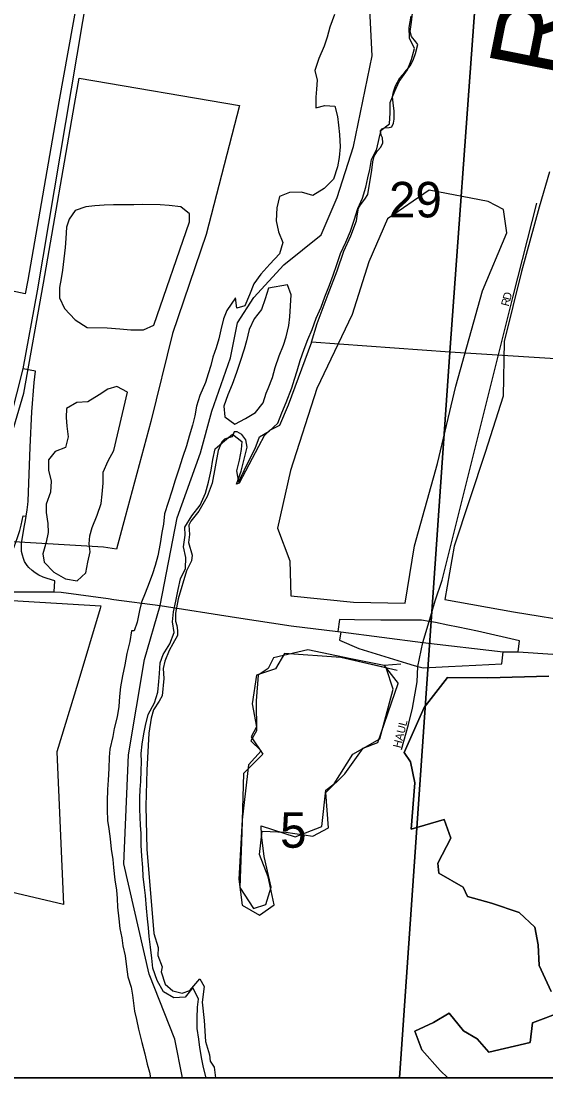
# Model space of a CAD drawing. Extents: x 0 to 34, y -6.2 to 22.
# Drawn here: x 6.003 to 6.622, y 14.39 to 15.636 of the extents above; entities that cross this region are included whole.
import ezdxf

# ---------------------------------------------------------------- set-up
doc = ezdxf.new("R2010")
doc.units = 0
for name, color, linetype in [('GM_X_City_Street', 7, 'Continuous'), ('GM_X_City_Street_Text', 7, 'Continuous'), ('GM_X_Corporation', 7, 'Continuous'), ('GM_X_Interchange_Ramps', 7, 'Continuous'), ('GM_X_Interstate_Route', 7, 'Continuous'), ('GM_X_Major_River', 7, 'Continuous'), ('GM_X_Major_River_Text', 7, 'Continuous'), ('GM_X_Minor_Lake', 7, 'Continuous'), ('GM_X_Section', 7, 'Continuous'), ('GM_X_Section_Text', 7, 'Continuous'), ('GM_X_State_Route', 7, 'Continuous'), ('GM_X_Township', 7, 'Continuous'), ('SH_Data', 7, 'Continuous')]:
    doc.layers.add(name, color=color, linetype=linetype)

msp = doc.modelspace()

# ---------------------------------------------------------------- linework, layer by layer
at = {"layer": 'GM_X_City_Street'}
msp.add_lwpolyline([(6.4516, 14.7775), (6.4595, 14.8069), (6.4644, 14.8262), (6.4697, 14.8571), (6.4706, 14.8751), (6.4766, 14.9035), (6.484, 14.9282), (6.4913, 14.9528), (6.4994, 14.9771), (6.583, 15.312), (6.6109, 15.4214)], dxfattribs=at)
at = {"layer": 'GM_X_Corporation'}
for points in [[(5.4833, 14.3902), (9.0755, 14.3902), (9.0755, 21.1902), (4.181, 21.1902)], [(6.0863, 15.7569), (6.0473, 15.541), (6.0106, 15.3305), (6.0078, 15.3144), (5.8578, 15.3464), (5.8706, 15.5168), (5.8395, 15.5185), (5.8415, 15.5423)], [(5.9675, 15.0677), (6.0061, 15.1973), (6.0293, 15.3272), (6.066, 15.5377), (6.0715, 15.5687), (6.2604, 15.5367), (6.2211, 15.3845), (6.1813, 15.2679), (6.1557, 15.1641), (6.1255, 15.0516), (6.1152, 15.0137), (6.0999, 15.016), (5.9475, 15.0249), (5.9675, 15.0677)], [(5.7838, 14.6859), (5.8622, 14.7617), (5.8945, 14.7931), (5.9217, 14.8222), (5.9352, 14.8512), (5.9529, 14.9009), (5.9722, 14.954), (6.0969, 14.9467), (6.0961, 14.9436), (6.0699, 14.8554), (6.045, 14.7747), (6.0527, 14.5945), (5.7641, 14.6624), (5.7838, 14.6859)]]:
    msp.add_lwpolyline(points, dxfattribs=at)
at = {"layer": 'GM_X_Interchange_Ramps'}
for points in [[(6.0417, 14.9633), (6.0425, 14.9763), (6.0337, 14.9788), (6.0288, 14.9805), (6.0238, 14.9829), (6.0194, 14.9856), (6.0157, 14.9884), (6.012, 14.9919), (6.0098, 14.9943), (6.0069, 14.9991), (6.0055, 15.0025), (6.0043, 15.0064), (6.0035, 15.0107), (6.0032, 15.0145), (6.0035, 15.0202), (6.0043, 15.0277), (6.0067, 15.0416), (6.008, 15.0474), (6.0089, 15.0523), (6.0101, 15.06), (6.0108, 15.0662), (6.0112, 15.07), (6.0134, 15.1338), (6.0155, 15.1755), (6.0182, 15.2102), (6.0199, 15.2235), (6.0052, 15.2262)], [(5.9741, 14.9631), (5.9777, 14.9734), (5.9919, 15.0102), (5.9945, 15.0161), (5.9967, 15.0218), (5.9985, 15.0271), (5.9998, 15.031), (6.0012, 15.0357), (6.0028, 15.0418), (6.004, 15.0475), (6.0051, 15.053), (6.0089, 15.0523)], [(6.484, 14.9282), (6.4751, 14.9297), (6.427, 14.9299), (6.3959, 14.9302), (6.3784, 14.9306), (6.3764, 14.9166)], [(6.5891, 14.8924), (6.5907, 14.9054), (6.5411, 14.9167), (6.5182, 14.9214), (6.5059, 14.9239), (6.4916, 14.9269), (6.484, 14.9282)], [(6.3797, 14.9159), (6.3784, 14.9061), (6.4011, 14.8965), (6.4574, 14.8793), (6.4664, 14.8762), (6.4706, 14.8751)], [(6.4706, 14.8751), (6.4769, 14.8735), (6.5067, 14.8752), (6.539, 14.8766), (6.5699, 14.8783), (6.5712, 14.8923)]]:
    msp.add_lwpolyline(points, dxfattribs=at)
at = {"layer": 'GM_X_Interstate_Route'}
msp.add_lwpolyline([(5.9164, 14.9622), (5.9164, 14.9622), (5.9488, 15.0343), (5.9755, 15.1099), (6.0052, 15.2262), (6.0222, 15.3181), (6.0956, 15.7552), (6.1327, 15.9696), (6.1711, 16.1965)], dxfattribs=at)
at = {"layer": 'GM_X_Major_River'}
for points in [[(6.3723, 15.6439), (6.3669, 15.6291), (6.3638, 15.617), (6.3604, 15.6064), (6.3538, 15.592), (6.3492, 15.578), (6.3518, 15.5666), (6.3513, 15.556), (6.3505, 15.5465), (6.3504, 15.534), (6.3611, 15.5365), (6.3728, 15.5357), (6.3761, 15.5236), (6.3772, 15.5133), (6.3783, 15.5023), (6.379, 15.4879), (6.3781, 15.4753), (6.3758, 15.4643), (6.3712, 15.4499), (6.3601, 15.4386), (6.3468, 15.4304), (6.3336, 15.4346), (6.3195, 15.4339), (6.3074, 15.4294), (6.3043, 15.4158), (6.3038, 15.4006), (6.3064, 15.3877), (6.3116, 15.3751), (6.3074, 15.3619), (6.2963, 15.3494), (6.2856, 15.3377), (6.2772, 15.3264), (6.2722, 15.3135), (6.2668, 15.3006), (6.2573, 15.2977), (6.2555, 15.3098), (6.2456, 15.2951), (6.2417, 15.2852), (6.2383, 15.2723), (6.2359, 15.2617)], [(6.2624, 15.131), (6.2601, 15.1185), (6.257, 15.106), (6.2592, 15.0927), (6.2657, 15.1063), (6.2722, 15.1192), (6.2787, 15.1324), (6.2841, 15.1461), (6.2955, 15.1528), (6.3054, 15.1619), (6.3104, 15.1744), (6.3154, 15.1865), (6.3219, 15.2039), (6.3254, 15.2138), (6.3285, 15.2236), (6.332, 15.2361), (6.3366, 15.2494), (6.3408, 15.2607), (6.3462, 15.2725), (6.3509, 15.2857), (6.3566, 15.299), (6.3612, 15.3111), (6.3666, 15.3247), (6.3709, 15.3365), (6.3751, 15.349), (6.3793, 15.3622), (6.3859, 15.3755), (6.3912, 15.3883), (6.3955, 15.4016), (6.4001, 15.4152), (6.4055, 15.4273), (6.4094, 15.4402), (6.4117, 15.4512), (6.414, 15.4611), (6.416, 15.4728), (6.4225, 15.4857), (6.4249, 15.4978), (6.4276, 15.5077), (6.4371, 15.5152), (6.4379, 15.5281), (6.438, 15.5403), (6.4434, 15.5535), (6.4488, 15.5649), (6.4583, 15.5785), (6.4633, 15.591), (6.4668, 15.6039), (6.4608, 15.616), (6.4605, 15.6286), (6.4629, 15.6418)], [(6.292, 15.1976), (6.2943, 15.2029), (6.2993, 15.2158), (6.3024, 15.2279), (6.307, 15.2416), (6.3124, 15.2541), (6.3155, 15.2639), (6.3186, 15.2772), (6.3198, 15.2874), (6.3215, 15.3132), (6.317, 15.325), (6.2946, 15.3214)], [(6.2946, 15.3214), (6.2908, 15.3088), (6.2865, 15.2963), (6.2777, 15.285), (6.2716, 15.2725), (6.2685, 15.2593), (6.2658, 15.2494), (6.2611, 15.2346), (6.2569, 15.2218), (6.2519, 15.2077), (6.2465, 15.1953), (6.2419, 15.182), (6.2429, 15.1695), (6.255, 15.161), (6.2676, 15.1674), (6.2793, 15.1746), (6.2881, 15.1859), (6.292, 15.1976)], [(6.2359, 15.2617), (6.2328, 15.2511), (6.229, 15.2398), (6.2266, 15.2299), (6.2235, 15.2201), (6.2201, 15.2102), (6.2135, 15.1947), (6.2097, 15.1822), (6.2077, 15.1708), (6.205, 15.1598), (6.2011, 15.1466), (6.1977, 15.1352), (6.193, 15.1216), (6.1888, 15.1079), (6.1845, 15.0947), (6.1807, 15.0818), (6.1764, 15.0685), (6.1718, 15.0553), (6.1706, 15.0431), (6.1686, 15.0333), (6.167, 15.0204), (6.1639, 15.0056), (6.1608, 14.9942), (6.1577, 14.9844), (6.1539, 14.9738), (6.1493, 14.9617), (6.145, 14.9511), (6.1423, 14.9412), (6.1396, 14.9276), (6.1361, 14.9173)], [(6.2209, 14.3902), (6.2179, 14.4026), (6.2161, 14.4121), (6.2135, 14.4258), (6.2124, 14.4357), (6.2106, 14.4482), (6.2103, 14.4604), (6.2108, 14.4736), (6.2119, 14.4831), (6.2052, 14.4968), (6.1964, 14.4855), (6.1828, 14.4844), (6.1707, 14.4917), (6.1632, 14.505), (6.158, 14.5195), (6.1569, 14.5313), (6.1555, 14.5442), (6.154, 14.5567), (6.153, 14.567), (6.1519, 14.5776), (6.1508, 14.5901), (6.1494, 14.6053), (6.1483, 14.6148), (6.1469, 14.6277), (6.1462, 14.6383), (6.1451, 14.6516), (6.1445, 14.6645), (6.1445, 14.6782), (6.1438, 14.6881), (6.1431, 14.6976), (6.1428, 14.7071), (6.1429, 14.7203), (6.1433, 14.7302), (6.1441, 14.7397), (6.1446, 14.7526), (6.1447, 14.7628), (6.1443, 14.7727), (6.1455, 14.7837), (6.1475, 14.7958), (6.1495, 14.8057), (6.1526, 14.8186), (6.1602, 14.8322), (6.1641, 14.8451), (6.1653, 14.8576), (6.1661, 14.8671), (6.167, 14.8796), (6.1704, 14.8894), (6.1781, 14.9019), (6.1835, 14.9152), (6.1813, 14.9277), (6.1825, 14.9398), (6.1852, 14.9523), (6.1879, 14.966), (6.191, 14.9785), (6.1968, 14.9906), (6.1972, 15.0039), (6.1943, 15.0164), (6.1963, 15.0301), (6.1959, 15.0396), (6.204, 15.0528), (6.2139, 15.0656), (6.2204, 15.0796), (6.2239, 15.0925), (6.227, 15.1066), (6.229, 15.1194), (6.2317, 15.132), (6.2428, 15.1414), (6.2523, 15.1493), (6.2632, 15.1405), (6.2624, 15.131)], [(6.1361, 14.9173), (6.1331, 14.9174), (6.1311, 14.9045), (6.1276, 14.8904), (6.1253, 14.8772), (6.1225, 14.8643), (6.1202, 14.8514), (6.119, 14.84), (6.1182, 14.8279), (6.1162, 14.8157), (6.1127, 14.8021), (6.1111, 14.7926), (6.1076, 14.7779), (6.1068, 14.7684), (6.1064, 14.7551), (6.1055, 14.7411), (6.1047, 14.7301), (6.1042, 14.7164), (6.1042, 14.7061), (6.1049, 14.6936), (6.1063, 14.6837), (6.1078, 14.672), (6.1092, 14.6598), (6.111, 14.6477), (6.1117, 14.6382), (6.1135, 14.6237), (6.1154, 14.6116), (6.116, 14.6017), (6.1167, 14.5915), (6.1182, 14.5778), (6.1193, 14.5664), (6.1215, 14.5554), (6.1229, 14.5459), (6.1255, 14.5341), (6.1273, 14.5212), (6.1288, 14.5094), (6.1325, 14.4973), (6.1343, 14.4878), (6.1365, 14.4688), (6.1391, 14.4589), (6.1413, 14.4475), (6.1453, 14.4319), (6.1487, 14.4186), (6.1516, 14.4065), (6.1542, 14.3969), (6.1554, 14.3902)]]:
    msp.add_lwpolyline(points, dxfattribs=at)
at = {"layer": 'GM_X_Minor_Lake'}
for points in [[(6.6259, 15.4584), (6.6139, 15.4167), (6.593, 15.3408), (6.5725, 15.2585), (6.5713, 15.1939), (6.5501, 15.1276), (6.5135, 15.0172), (6.5025, 14.9542), (6.5836, 14.9395), (6.6609, 14.927), (6.7156, 14.9356), (6.7213, 15.0046), (6.7237, 15.1064), (6.705, 15.2139), (6.7037, 15.3233), (6.6995, 15.392), (6.6809, 15.4476)], [(6.5537, 15.4234), (6.4839, 15.4369), (6.4348, 15.403), (6.4129, 15.3522), (6.3932, 15.2903), (6.3517, 15.2028), (6.3205, 15.1061), (6.3053, 15.0382), (6.3199, 14.9998), (6.3208, 14.9584), (6.3947, 14.9509), (6.4558, 14.9499), (6.4668, 15.0174), (6.4939, 15.1145), (6.5156, 15.2056), (6.547, 15.3182), (6.5758, 15.3865), (6.5718, 15.4142)], [(6.2016, 15.3993), (6.2014, 15.4088), (6.1913, 15.4173), (6.1773, 15.4187), (6.1667, 15.4196), (6.1458, 15.4198), (6.1356, 15.4196), (6.1216, 15.4194), (6.1117, 15.4196), (6.1007, 15.4193), (6.0897, 15.4183), (6.0791, 15.4173), (6.0665, 15.413), (6.0596, 15.4028), (6.0564, 15.393), (6.0555, 15.3797), (6.0549, 15.3691), (6.0515, 15.3425), (6.0499, 15.3327), (6.0482, 15.3221), (6.0481, 15.3099), (6.054, 15.2973), (6.0667, 15.2838), (6.0809, 15.2749), (6.1044, 15.2746), (6.1192, 15.2733), (6.1324, 15.2723), (6.1472, 15.2721), (6.1594, 15.2777)], [(6.5718, 15.4142), (6.5537, 15.4234)], [(6.1594, 15.2777), (6.2016, 15.3993)], [(6.1284, 15.1987), (6.1156, 15.2053), (6.1053, 15.2021), (6.095, 15.1954), (6.0816, 15.1872), (6.0684, 15.1866), (6.0565, 15.1792), (6.056, 15.1689), (6.0566, 15.1587), (6.0583, 15.1458), (6.0551, 15.1333), (6.0429, 15.1285), (6.0352, 15.1187), (6.0351, 15.1066), (6.0383, 15.0936), (6.0374, 15.0807), (6.0322, 15.0664), (6.0325, 15.0569), (6.0342, 15.0439), (6.0348, 15.0333), (6.0324, 15.0216), (6.0284, 15.008), (6.0302, 14.9984), (6.0414, 14.9865), (6.0553, 14.9784), (6.0689, 14.9763), (6.0793, 14.9856), (6.0817, 14.9981), (6.0842, 15.0102), (6.0831, 15.0197), (6.084, 15.0292), (6.0868, 15.0391), (6.0927, 15.0538), (6.0971, 15.0674), (6.0983, 15.0784), (6.0997, 15.0913), (6.0998, 15.1042), (6.1057, 15.1178), (6.1123, 15.1298)], [(6.1123, 15.1298), (6.1284, 15.1987)], [(6.4508, 14.8778), (6.4311, 14.8763), (6.3917, 14.8844), (6.3409, 14.8949), (6.3006, 14.8856), (6.2941, 14.8727), (6.2823, 14.8651), (6.2799, 14.8348), (6.2804, 14.7995), (6.2739, 14.7877), (6.286, 14.7759), (6.2711, 14.7592), (6.2635, 14.6943), (6.2597, 14.6245), (6.2637, 14.5937), (6.2838, 14.5819), (6.3013, 14.5943), (6.2943, 14.6274), (6.2838, 14.6536), (6.287, 14.681), (6.3151, 14.6797), (6.3469, 14.675), (6.3655, 14.6848), (6.362, 14.7266), (6.3845, 14.7485), (6.4063, 14.7788), (6.4234, 14.7856), (6.4473, 14.855)], [(6.4332, 14.8736), (6.3799, 14.886), (6.3136, 14.8904), (6.3029, 14.8726), (6.2804, 14.8648), (6.2753, 14.831), (6.2805, 14.804), (6.2743, 14.7923), (6.2879, 14.7717), (6.265, 14.749), (6.2631, 14.6795), (6.2608, 14.6146), (6.277, 14.5899), (6.2914, 14.5944), (6.2976, 14.6149), (6.2895, 14.651), (6.2862, 14.6768), (6.2859, 14.6874), (6.326, 14.6744), (6.3576, 14.6864), (6.362, 14.7293), (6.3719, 14.7368), (6.3941, 14.7717), (6.4257, 14.7898), (6.4416, 14.8486)], [(6.4462, 14.8706), (6.3799, 14.886), (6.3136, 14.8904), (6.3029, 14.8726), (6.2804, 14.8648), (6.2753, 14.831), (6.2805, 14.804), (6.2743, 14.7923), (6.2879, 14.7717), (6.265, 14.749), (6.2631, 14.6795), (6.2608, 14.6146), (6.277, 14.5899), (6.2914, 14.5944), (6.2976, 14.6149), (6.2895, 14.651), (6.2862, 14.6768), (6.2859, 14.6874), (6.326, 14.6744), (6.3576, 14.6864), (6.362, 14.7293), (6.3719, 14.7368), (6.3941, 14.7717), (6.4257, 14.7898), (6.4416, 14.8486)], [(6.4311, 14.8763), (6.4473, 14.855)], [(6.4416, 14.8486), (6.4332, 14.8736)], [(6.6253, 14.8638), (6.5532, 14.8618), (6.5058, 14.8623), (6.4782, 14.8268), (6.4544, 14.7737), (6.462, 14.7627), (6.4671, 14.738), (6.4627, 14.6833), (6.5018, 14.6949), (6.5096, 14.6729), (6.4943, 14.6433), (6.4954, 14.6315), (6.5241, 14.6151), (6.5294, 14.6041), (6.5574, 14.596), (6.59, 14.5852), (6.6088, 14.5677), (6.6125, 14.5472), (6.6139, 14.5225), (6.6281, 14.492)], [(6.6281, 14.492), (6.6139, 14.5225), (6.6125, 14.5472), (6.6088, 14.5677), (6.59, 14.5852), (6.5574, 14.596), (6.5294, 14.6041), (6.5241, 14.6151), (6.4954, 14.6315), (6.4943, 14.6433), (6.5096, 14.6729), (6.5018, 14.6949), (6.4627, 14.6833), (6.4671, 14.738), (6.462, 14.7627), (6.4544, 14.7737), (6.4782, 14.8268), (6.5058, 14.8623), (6.5532, 14.8618), (6.6253, 14.8638)], [(6.6424, 14.4688), (6.6059, 14.4549), (6.6031, 14.4318), (6.5545, 14.4206), (6.5406, 14.4362), (6.5247, 14.4458), (6.5077, 14.4663), (6.4891, 14.4554), (6.467, 14.4452), (6.4753, 14.4232), (6.4971, 14.3988), (6.5062, 14.3902)], [(6.5062, 14.3902), (6.4971, 14.3988), (6.4753, 14.4232), (6.467, 14.4452), (6.4891, 14.4554), (6.5077, 14.4663), (6.5247, 14.4458), (6.5406, 14.4362), (6.5545, 14.4206), (6.6031, 14.4318), (6.6059, 14.4549), (6.6424, 14.4688)]]:
    msp.add_lwpolyline(points, dxfattribs=at)
at = {"layer": 'GM_X_Section'}
for p, q in [((6.2319, 14.3902), (6.449, 14.3902)), ((6.449, 14.3902), (7.4483, 14.3902))]:
    msp.add_line(p, q, dxfattribs=at)
msp.add_lwpolyline([(7.5576, 16.2055), (7.497, 15.1834), (6.5086, 15.2458), (6.5658, 16.0353), (6.5704, 16.0443), (6.5735, 16.0466), (6.5731, 16.0496), (6.5693, 16.0527), (6.5637, 16.0565), (6.5603, 16.0599), (6.5603, 16.0637), (6.5622, 16.0671), (6.5676, 16.0735), (6.582, 16.0863), (6.5935, 16.0976), (6.6121, 16.1149), (6.632, 16.1352), (6.6415, 16.1465), (6.6507, 16.159), (6.658, 16.1722), (6.671, 16.2039), (6.6853, 16.2364), (6.6948, 16.25), (6.6949, 16.2608)], close=True, dxfattribs=at)
for points in [[(6.5658, 16.0353), (6.5086, 15.2458), (6.3451, 15.2574), (6.352, 15.2797), (6.3651, 15.3141), (6.3755, 15.3417), (6.3836, 15.3648), (6.3917, 15.3829), (6.3982, 15.4007), (6.3994, 15.409), (6.4006, 15.4154), (6.4029, 15.4196), (6.4082, 15.426), (6.4117, 15.4316), (6.4164, 15.4604), (6.4176, 15.4702), (6.4192, 15.477), (6.423, 15.4831), (6.4272, 15.4876), (6.4295, 15.4925), (6.4291, 15.4986), (6.4276, 15.5016), (6.4265, 15.5069), (6.4288, 15.5092), (6.4315, 15.5103), (6.4368, 15.5106), (6.4402, 15.5114), (6.4421, 15.5159), (6.4429, 15.5205), (6.4426, 15.5299), (6.4415, 15.5398), (6.4408, 15.547), (6.442, 15.5527), (6.4443, 15.5598), (6.4493, 15.5693), (6.4554, 15.5761), (6.4619, 15.5836), (6.4657, 15.5912), (6.468, 15.598), (6.4707, 15.6086), (6.4685, 15.6116), (6.4632, 15.6181), (6.4617, 15.6238), (6.4633, 15.6347), (6.4657, 15.6559)], [(6.449, 14.3902), (6.5086, 15.2458), (6.3451, 15.2574), (6.3177, 15.1833), (6.3077, 15.1592), (6.2959, 15.1535), (6.2895, 15.1471), (6.2826, 15.1347), (6.2599, 15.0913), (6.2569, 15.0901), (6.2623, 15.1056), (6.2693, 15.1336), (6.2678, 15.1424), (6.2633, 15.1488), (6.2577, 15.1519), (6.2539, 15.1519), (6.2516, 15.1459), (6.2463, 15.1444), (6.2428, 15.1433), (6.2394, 15.1399), (6.2352, 15.1297), (6.2281, 15.0915), (6.2223, 15.0756), (6.2187, 15.0693), (6.2124, 15.0582), (6.2028, 15.0465), (6.2005, 15.042), (6.2016, 15.031), (6.2004, 15.0215), (6.2045, 15.0064), (6.2037, 14.9999), (6.1979, 14.9879), (6.1879, 14.955), (6.1851, 14.9379), (6.1851, 14.9288), (6.1865, 14.9235), (6.1873, 14.9178), (6.1872, 14.9118), (6.1819, 14.902), (6.1773, 14.894), (6.1723, 14.8816), (6.1703, 14.8729), (6.171, 14.8611), (6.169, 14.8407), (6.1655, 14.8343), (6.159, 14.8241), (6.1563, 14.8142), (6.1536, 14.7965), (6.151, 14.7529), (6.15, 14.7105), (6.1512, 14.6597), (6.1593, 14.5604), (6.1645, 14.5437), (6.1641, 14.5346), (6.1693, 14.521), (6.1681, 14.5153), (6.1729, 14.5005), (6.1816, 14.4928), (6.1926, 14.4901), (6.2017, 14.4931), (6.2135, 14.507), (6.2187, 14.4979), (6.2164, 14.4794), (6.2189, 14.4578), (6.2202, 14.4331), (6.2251, 14.4172), (6.2258, 14.41), (6.2307, 14.4028), (6.2319, 14.3902)], [(7.4483, 14.3902), (7.497, 15.1834), (6.5086, 15.2458), (6.449, 14.3902)]]:
    msp.add_lwpolyline(points, dxfattribs=at)
at = {"layer": 'GM_X_State_Route'}
for points in [[(5.9741, 14.9631), (5.9741, 14.9631), (6.0417, 14.9633), (6.05, 14.9627), (6.1057, 14.9552), (6.1123, 14.9543)], [(6.1123, 14.9543), (6.1667, 14.9471), (6.257, 14.9328), (6.3212, 14.9233), (6.3764, 14.9166), (6.3797, 14.9159), (6.4766, 14.9035), (6.5712, 14.8923), (6.5891, 14.8924), (6.6708, 14.887), (6.7397, 14.8822)]]:
    msp.add_lwpolyline(points, dxfattribs=at)
at = {"layer": 'GM_X_Township'}
msp.add_line((3.5084, 14.3902), (6.1932, 14.3902), dxfattribs=at)
msp.add_lwpolyline([(6.1932, 14.3902), (6.1841, 14.4359), (6.154, 14.5126), (6.1239, 14.6426), (6.1293, 14.7712), (6.1485, 14.8834), (6.1667, 14.9471), (6.1868, 15.0504), (6.2142, 15.127), (6.2279, 15.1763), (6.2498, 15.2393), (6.258, 15.2803), (6.2771, 15.3104), (6.3127, 15.3487), (6.3565, 15.3843), (6.3757, 15.4281), (6.3948, 15.4884), (6.4167, 15.5951), (6.414, 15.6499)], dxfattribs=at)
at = {"layer": 'SH_Data'}
msp.add_lwpolyline([(9.0755, 21.1902), (9.0755, 14.3902), (2.2755, 14.3902), (2.2755, 21.1902)], close=True, dxfattribs=at)

# ---------------------------------------------------------------- texts
at = {"layer": 'GM_X_City_Street_Text'}
for s, rotation, p in [('D', 74.9193, (6.5797, 15.3064)), ('R', 75.7929, (6.5778, 15.2992)), ('HAUL', 75.6132, (6.4503, 14.7784))]:
    msp.add_text(s, height=0.00947, rotation=rotation, dxfattribs=at).set_placement(p)
at = {"layer": 'GM_X_Major_River_Text'}
msp.add_text('River', height=0.09472, rotation=78.7687, dxfattribs=at).set_placement((6.6467, 15.5642))
at = {"layer": 'GM_X_Section_Text'}
for s, height, p in [('29', 0.04186, (6.4367, 15.4047)), ('5', 0.0419, (6.3083, 14.6615))]:
    msp.add_text(s, height=height, rotation=0, dxfattribs=at).set_placement(p)

doc.saveas('drawing.dxf')
